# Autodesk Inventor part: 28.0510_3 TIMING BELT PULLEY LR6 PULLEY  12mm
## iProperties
Created: 2007-06
Part Number: 28.0510_3 TIMING BELT PULLEY LR6 PULLEY  12mm
Document SubType Name: Modeling
Designer: Andy Moles
Material: Aluminum-6061
Density: 2.71 g/cm^3
Author: Andy Moles
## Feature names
1. Revolution1
2. Extrusion1
3. Circular Pattern1
4. Extrusion2
5. Mirror1
6. Extrusion3
